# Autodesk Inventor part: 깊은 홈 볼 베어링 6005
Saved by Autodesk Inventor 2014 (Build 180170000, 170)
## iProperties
Created: 2025-12
Part Number: 깊은 홈 볼 베어링 6005
Material: 일반
Document SubType Name: Modeling
Designer: dg
Density: 1 g/cm^3
Appearance: 기본값
Author: dg
Author: jhkim
Description: 깊은 그루브 볼 베어링
Creation Date: 2025-11-19
Sending System: Autodesk Inventor 2026
Preprocessor: ST-DEVELOPER v20.1
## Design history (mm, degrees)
node "깊은 홈 볼 베어링 60051"
body "Solid1"
node "Solid1_1"
node "Solid1_2"
node "Solid1_3"
node "Solid1_4"
node "Solid1_5"
node "Solid1_6"
node "Solid1_7"
node "Solid1_8"
node "Solid1_9"
node "Solid1_10"
node "Solid1_11"
node "기준1"
node "기준2"
node "기준3"
node "기준4"
node "기준5"
node "기준6"
node "기준7"
node "기준8"
node "기준9"
node "기준10"
node "기준11"
node "기준12"
